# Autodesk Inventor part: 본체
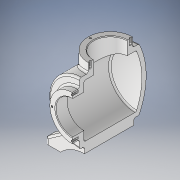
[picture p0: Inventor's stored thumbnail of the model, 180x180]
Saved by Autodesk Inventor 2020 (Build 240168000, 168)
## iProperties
Created: 2023-12
Part Number: 본체
Material: 일반
Document SubType Name: Modeling
Designer: 1강의실14
Density: 1 g/cm^3
Appearance: 기본값
Mass: 480.256 g
Surface Area: 1060.44 cm^2
Volume: 480.256 cm^3
Author: 1강의실14
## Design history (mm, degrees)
sketch "스케치4"
  geometry: L1 (62, -40)-(-62, -40); L2 (-62, -40)-(-62, 40); L3 (-62, 40)-(62, 40); L4 (62, 40)-(62, -40); L5 (62, -40)-(-62, 40); L6 (-62, -40)-(62, 40); L7 (-54, -13)-(-62, -13); L8 (-62, -13)-(-62, -27); L9 (-62, -27)-(-54, -27); L10 (-54, -27)-(-54, -13); L11 (-54, -13)-(-62, -27); L12 (-62, -13)-(-54, -27); L13 (-62, 27)-(-54, 27); L14 (-54, 27)-(-54, 13); L15 (-54, 13)-(-62, 13); L16 (-62, 13)-(-62, 27); L17 (-62, 27)-(-54, 13); L18 (-54, 27)-(-62, 13); L19 (-62, 20)-(-47, 20); A1 r 7 centre (-54, -20) between (-54, -13) and (-54, -27); A2 r 7 centre (-54, 20) between (-54, 27) and (-54, 13); 8 further points
  constraints: 38 end point, 8 midpoint, 6 parallel, 5 point on circle, 4 horizontal, 3 perpendicular, 2 centre point, 2 point on line
  dimensions: "d9" = 124 distance of L2.end L3.end; "d10" = 80 distance of L1.end L2.end; "d63" = 14 diameter of A1; "d64" = 8 distance of L9.end L8.end; "d65" = 14 distance of L8.end L7.end; "d66" = 20 distance from line of L1 A1.centre; "d67" = 14 diameter of A2; "d68" = 8 distance of L14.end L15.end; "d69" = 14 distance of L13.end L14.end; "d70" = 40 distance from line of A1.centre L19
sketch "스케치5" dims "d17" = 226
  geometry: L1 (127, 60)-(27, 60); L2 (27, 60)-(27, -60); L3 (27, -60)-(127, -60); L4 (127, -60)-(127, 60); L5 (127, 60)-(27, -60); L6 (27, 60)-(127, -60); L7 (0, 40)-(0, -40) reference; L8 (0, 40)-(10, 40) reference; L9 (77, 60)-(77, -60); L10 (27, 48)-(127, 48); L11 (127, 48)-(127, -60); L12 (127, -60)-(27, -60); L13 (27, -60)-(27, 48); L14 (27, 48)-(127, -60); L15 (127, 48)-(27, -60); L16 (-81.2, 0)-(235.2, 0) reference; L17 (0, -105.2)-(0, 211.2) reference; 9 further points
  constraints: 26 end point, 9 midpoint, 4 parallel, 3 horizontal, 2 perpendicular, 1 vertical alignment, 3 other
  dimensions: "d13" = 100 distance of L3.end L2.end; "d14" = 120 distance of L2.end L1.end; "d18" = 100 distance of L11.end L12.end; "d19" = 108 distance of L10.end L11.end; "d21" = 60 distance between parallel lines of L16 L1; "d22" = 77 distance between parallel lines of L9 L17
revolve "회전2" sketch "스케치5" stored, may be unused: angle "d20" = 90 deg
feature "쉘1" dims "d23" = 7
extrude "돌출2" join sketch "스케치4" distance "d24" = 10; taper "d25" = 0 deg
node "작업 평면2"
sketch "스케치6"
  geometry: C1 r 50 at (0, 0) reference; C2 r 36 at (0, 0); 1 further point
  constraints: 1 centre point, 1 coincident
  dimensions: "d27" = 72 diameter of C2
extrude "돌출3" join sketch "스케치6" stored distance "d28" = 10; taper "d29" = 0 deg
sketch "스케치7"
  geometry: C1 r 36 at (0, 0) reference; 2 further points
  constraints: 1 coincident
hole "구멍1" sketch "스케치7" at (0, 0) diameter "d30" = 54; stored, may be unused: countersink angle "d34" = 90 deg, drill point angle "d36" = 118 deg; dims "d31" = 9, "d32" = 4, "d33" = 2, "d35" = 20
node "작업 평면3"
sketch "스케치8"
  geometry: L1 (36, 60)-(-36, 60) reference; C1 r 36 at (0, -2); 1 further point
  constraints: 1 centre point, 1 vertical alignment
  dimensions: "d38" = 72 diameter of C1; "d39" = 62 distance from line of C1.centre L1
extrude "돌출4" join sketch "스케치8" stored distance "d40" = 10; taper "d41" = 0 deg
sketch "스케치9"
  geometry: C1 r 36 at (0, 0) reference; 2 further points
  constraints: 1 coincident
hole "구멍2" sketch "스케치9" at (0, 0) diameter "d42" = 54; stored, may be unused: countersink angle "d46" = 90 deg, drill point angle "d48" = 118 deg; dims "d43" = 9, "d44" = 4, "d45" = 2, "d47" = 50
sketch "스케치10"
  geometry: L1 (62, 40)-(-62, 40) reference; L2 (-5, -40)-(5, -40); L3 (5, -40)-(5, 40); L4 (5, 40)-(-5, 40); L5 (-5, 40)-(-5, -40); L6 (-5, -40)-(5, 40); L7 (5, -40)-(-5, 40); 2 further points
  constraints: 12 end point, 2 midpoint, 2 parallel, 1 horizontal, 1 perpendicular, 1 point on line
  dimensions: "d49" = 10 distance of L2.start L2.end
extrude "돌출5" join sketch "스케치10" stored distance "d50" = 10; taper "d51" = 0 deg
sketch "스케치11"
  geometry: L1 (62, 0)-(62, 10) reference; L2 (62, 10)-(29.632, 32.664); 1 further point
  constraints: 2 end point
  dimensions: "d52" = 55 deg angle of L1 L2
feature "리브1" sketch "스케치11" dims "d53" = 1, "d54" = 80, "d55" = 0, "d56" = 0, "d57" = 1, "d58" = 1
sketch "스케치12"
  geometry: L1 (23.5, 0)-(100.5, 0); L2 (62, 17)-(62, 0); A1 r 52.096 centre (62, -35.096) between (100.5, 0) and (23.5, 0); 1 further point
  constraints: 4 end point, 3 point on circle, 1 centre point, 1 coincident, 1 horizontal, 1 midpoint, 1 vertical
  dimensions: "d59" = 77 distance of L1.start L1.end; "d60" = 17 distance of L2.end L2.start
extrude "돌출6" cut sketch "스케치12" extent not by distance; stored distance "d61" = 0; taper "d62" = 0 deg
extrude "돌출7" cut sketch "스케치4" distance "d71" = 25; taper "d72" = 0 deg
extrude "돌출8" join sketch "스케치4" distance "d73" = 6; taper "d74" = 0 deg
sketch "스케치13"
  geometry: A1 r 7 centre (54, -20) between (54, -13) and (54, -27) reference; A2 r 7 centre (54, 20) between (54, 27) and (54, 13) reference; 3 further points
  constraints: 2 coincident
hole "구멍3" sketch "스케치13" at (54, -20), (54, 20) diameter "d75" = 9; stored, may be unused: countersink angle "d79" = 90 deg, drill point angle "d81" = 118 deg; dims "d76" = 9, "d77" = 4, "d78" = 2, "d80" = 10
sketch "스케치14" dims "d82" = 65
  geometry: L1 (-36, -62)-(36, -62) reference; L2 (0, -2)-(0, 32.5); C1 r 27 at (0, 0) reference; 1 further point
  constraints: 2 end point, 1 coincident, 1 vertical, 1 vertical alignment, 2 other
hole "구멍4" sketch "스케치14" at (0, 32.5) diameter "d84" = 3.242; stored, may be unused: countersink angle "d88" = 90 deg, drill point angle "d90" = 118 deg; dims "d85" = 8, "d86" = 4, "d87" = 2, "d89" = 10
sketch "스케치15"
  geometry: L1 (0, 0)-(0, 32.5); C1 r 27 at (0, 0) reference; 1 further point
  constraints: 2 end point, 1 vertical
  dimensions: "d94" = 32.5 distance of L1.start L1.end
hole "구멍5" sketch "스케치15" at (0, 32.5) diameter "d95" = 3.242; stored, may be unused: countersink angle "d99" = 90 deg, drill point angle "d101" = 118 deg; dims "d96" = 8, "d97" = 4, "d98" = 2, "d100" = 10
chamfer "모따기1" distance "d105" = 1; stored, may be unused: second distance "d106" = 2, angle "d107" = 45 deg
fillet "모깎기1" dims "d108" = 3
node "작업 평면4"
sketch "스케치16"
  geometry: L1 (36, 60.168)-(-36, 60.168) reference; 3 further points
  constraints: 1 midpoint, 1 vertical alignment, 1 other
  dimensions: "d110" = 62 distance from line of point (0, -1.832) L1
feature "엠보싱1" sketch "스케치16" dims "d9" = 124, "d10" = 80, "d63" = 14, "d64" = 8, "d65" = 14, "d66" = 20, "d67" = 14, "d68" = 8, "d69" = 14, "d70" = 40, "d111" = 0.5, "d112" = 0
feature "분할1"
node "솔리드2"
mirror "미러1"
mirror "미러2"
pattern_circular "원형 패턴1" dims angle "d92" = 360 deg
pattern_circular "원형 패턴2" dims angle "d103" = 360 deg
feature "A9D066F2-1C7D-4E18-AEED-F7BC21143FA4" dims "d30" = 54, "d31" = 9, "d32" = 4, "d33" = 2, "d34" = 90 deg, "d35" = 20, "d36" = 118 deg
other parameters: "d26" = 12, "d37" = 142
